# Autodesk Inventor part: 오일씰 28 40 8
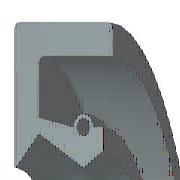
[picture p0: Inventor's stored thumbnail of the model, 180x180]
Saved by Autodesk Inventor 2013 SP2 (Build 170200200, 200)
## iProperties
IsCustomPart: 1
Created: 2012-02
Part Number: 오일씰 28 40 8
Material: 고무
Description: Oil-seal
Document SubType Name: Modeling
Standard: KS B 2804
Designer: mduedu
Standards Organization: KS
Language: en-US
Size Designation: D - 28 40 8
Categories: <MemberInstance><Categories><Category DisplayName="Shaft Parts" InternalName="7f7aeb1f-a693-4053-b835-cee3144e0d98" Mnemonic="SHFT"><Category DisplayName="Seali
Density: 0.93 g/cm^3
Mass: 2.83894 g
Surface Area: 40.7521 cm^2
Volume: 3.05262 cm^3
Author: mduedu
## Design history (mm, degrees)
sketch "Sketch1"
  geometry: L1 (0, 20)-(8, 20); L2 (8, 18.25)-(1.75, 18.25); L3 (1.75, 15.75)-(4.9, 14); L4 (4.9, 14)-(0, 14); L5 (0, 0)-(9.586, 0) reference; L6 (4.9, 14)-(6.3, 14.875); L7 (0, 18)-(0, -3) reference; L8 (-1.941, 0)-(11.507, 0) reference; L9 (4.2, 16.1)-(1.75, 16.71); L10 (1.75, 16.71)-(1.75, 18.25); L11 (0, 20)-(0, 14.088); L12 (4.9, 14)-(0, 14); L13 (1.75, 15.75)-(0.152, 14.028); L14 (8, 20)-(8, 18.25); L15 (5.6, 16.1)-(6.3, 16.1); L16 (6.3, 16.1)-(6.3, 14.875); C1 r 0.455 at (4.9, 16.1); A1 r 0.7 centre (4.9, 16.1) between (5.6, 16.1) and (4.2, 16.1); A2 r 0.088 centre (0.087, 14.088) between (0, 14.088) and (0.152, 14.028); 1 further point
  constraints: 28 end point, 5 horizontal alignment, 5 point on line, 4 point on circle, 4 vertical alignment, 3 centre point, 3 tangent, 2 collinear, 2 horizontal, 2 perpendicular, 1 coincident, 1 parallel
  dimensions: "d0" = 40 diameter of L1 L5 (= SD2); "d1" = 1.75 distance of L1.end L2.start (= SD); "d2" = 0.91 diameter of C1 (= SPDI); "d3" = 1.4 diameter of A1 (= SPDA); "d4" = 28 diameter of L3.end L5 (= NND); "d5" = 31.5 diameter of L3.start L5 (= TKDM); "d7" = 33.42 diameter of L9.end L5 (= TKDM + 0.24 x SWDT); "d8" = 1.75 distance between parallel lines of L11 L10 (= SD); "d9" = 4.9 distance from line of L11 C1.centre (= SPDST); "d10" = 32.2 diameter of C1.centre L5 (= HLDM); "d11" = 0.0875 radius of A2 (= 0.25 x LAB); "d12" = 6.3 distance between parallel lines of L11 L16 (= SDI); "d13" = 29.75 diameter of L6.end L5 (= ABDM); "d14" = 8 distance from line of L11 L1.end (= SWDT)
revolve "Body" stored, may be unused: angle "d17" = 90 deg
revolve "Spring1" stored, may be unused: angle "d18" = 90 deg
fillet "Fillet1" dims "d6" = 0.4 (= RR)
body "Solid1"
other parameters: "SD2" = 40 [user parameter; used in 1 equation term], "SWDT" = 8 [user parameter; used in 2 equation terms], "RR" = 0.4 [user parameter; used in 1 equation term], "SD" = 1.75 [user parameter; used in 2 equation terms], "NND" = 28 [user parameter; used in 1 equation term], "SPDA" = 1.4 [user parameter; used in 1 equation term], "SPDI" = 0.91 [user parameter; used in 1 equation term], "TKDM" = 31.5 [user parameter; used in 2 equation terms], "HLDM" = 32.2 [user parameter; used in 1 equation term], "ABDM" = 29.75 [user parameter; used in 1 equation term], "SDI" = 6.3 [user parameter; used in 1 equation term], "SPDST" = 4.9 [user parameter; used in 1 equation term], "LAB" = 0.35 [user parameter; used in 1 equation term], "d15" = 0, "d16" = 0, "d19" = 0
